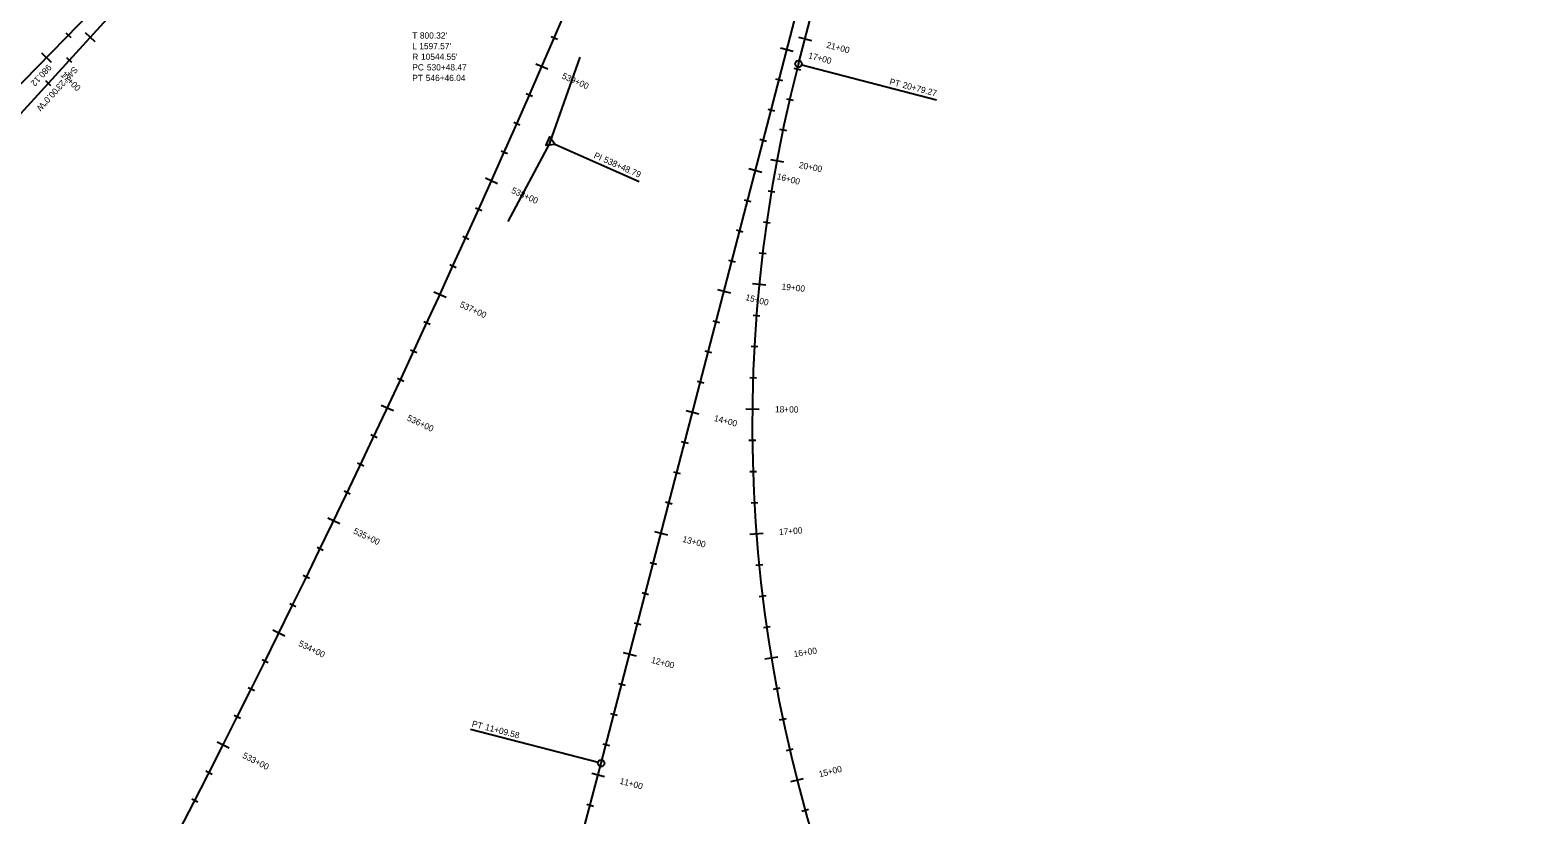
# Model space of a CAD drawing. Extents: x 2300830 to 2307917, y 756066 to 766359.
# Drawn here: x 2303759 to 2304965, y 762132 to 762760 of the extents above; entities that cross this region are included whole.
import ezdxf

# ---------------------------------------------------------------- set-up
doc = ezdxf.new("R2010")
doc.units = 0
for name, color, linetype in [('Default', 7, 'Continuous'), ('Draft_Bearing Label', 7, 'Continuous'), ('Draft_Curve Data Label', 7, 'Continuous'), ('Draft_Station Cardinal Lines', 7, 'Continuous'), ('Draft_Station Cardinal Points', 7, 'Continuous'), ('Draft_Station Labels Major', 7, 'Continuous'), ('Draft_Station Ticks Major', 7, 'Continuous'), ('Draft_Station Ticks Minor', 7, 'Continuous'), ('Geom_Baseline', 7, 'Continuous')]:
    doc.layers.add(name, color=color, linetype=linetype)

msp = doc.modelspace()

# ---------------------------------------------------------------- linework, layer by layer
at = {"layer": 'Default'}
for p, q in [((2304215.7, 762173.2), (2304540, 763420.7)), ((2304103.9, 763080), (2303443.2, 762356)), ((2303597.1, 762560.2), (2304068.2, 763040.9)), ((2304373.6, 762733), (2304449.9, 763026.4))]:
    msp.add_line(p, q, dxfattribs=at)
for centre, radius, start, end in [((2294501, 766942), 10544.6, 331.8357, 340.5164), ((2305484.2, 762444.3), 1147.5, 165.4287, 243.12), ((2304169.7, 761693), 983.5, 137.6167, 272.5224), ((2298663, 763616.6), 5737.3, 339.43722, 345.42872)]:
    msp.add_arc(centre, radius, start, end, dxfattribs=at)
at = {"layer": 'Draft_Station Cardinal Lines'}
for p, q in [((2304174.8, 762670.5), (2304198.9, 762738.4)), ((2304376.2, 762732.3), (2304484, 762704.3)), ((2304174.8, 762670.5), (2304140.9, 762607)), ((2304178.7, 762668.8), (2304246.2, 762639)), ((2304213.2, 762173.8), (2304111.2, 762200.3))]:
    msp.add_line(p, q, dxfattribs=at)
msp.add_lwpolyline([(2304178.6, 762668.8), (2304174.4, 762674.7), (2304171.5, 762668.1)], close=True, dxfattribs=at)
at = {"layer": 'Draft_Station Cardinal Points'}
for p, q in [((2304373.6, 762733), (2304373.6, 762733)), ((2304484, 762704.3), (2304484, 762704.3)), ((2304174.8, 762670.5), (2304174.8, 762670.5)), ((2304246.2, 762639), (2304246.2, 762639)), ((2304111.2, 762200.3), (2304111.2, 762200.3)), ((2304215.7, 762173.2), (2304215.7, 762173.2))]:
    msp.add_line(p, q, dxfattribs=at)
for centre in [(2304373.6, 762733), (2304215.7, 762173.2)]:
    msp.add_circle(centre, 2.67, dxfattribs=at)
at = {"layer": 'Draft_Station Ticks Major'}
for p, q in [((2303810.8, 762750.8), (2303802.9, 762758)), ((2304373.7, 762754.4), (2304383.9, 762751.7)), ((2303767.8, 762742), (2303775.4, 762734.5)), ((2304359.1, 762745.9), (2304369.4, 762743.3)), ((2304163.4, 762733.2), (2304173.1, 762729)), ((2304351.1, 762656.6), (2304361.5, 762654.6)), ((2304334, 762649.2), (2304344.2, 762646.5)), ((2304123, 762641.8), (2304132.7, 762637.4)), ((2304081.8, 762550.7), (2304091.5, 762546.3)), ((2304308.8, 762552.4), (2304319.1, 762549.7)), ((2304336.9, 762557.2), (2304347.5, 762556.1)), ((2304039.7, 762460), (2304049.4, 762455.5)), ((2304283.6, 762455.6), (2304293.9, 762452.9)), ((2304331.4, 762456.9), (2304342.1, 762456.8)), ((2303996.8, 762369.8), (2304006.4, 762365.2)), ((2304258.5, 762358.8), (2304268.8, 762356.1)), ((2304334.7, 762356.5), (2304345.3, 762357.3)), ((2303953, 762279.9), (2303962.6, 762275.2)), ((2304233.3, 762262), (2304243.6, 762259.3)), ((2304346.7, 762256.8), (2304357.2, 762258.5)), ((2303908.4, 762190.5), (2303917.9, 762185.7)), ((2304208.2, 762165.2), (2304218.4, 762162.6)), ((2304367.4, 762158.5), (2304377.6, 762161.1))]:
    msp.add_line(p, q, dxfattribs=at)
at = {"layer": 'Draft_Station Ticks Minor'}
for p, q in [((2303787.2, 762758), (2303791.1, 762754.2)), ((2304175.7, 762755.1), (2304180.8, 762752.9)), ((2303792, 762734.1), (2303787.9, 762737.8)), ((2304369.9, 762729.5), (2304375.2, 762728.2)), ((2303775.1, 762715.6), (2303771.1, 762719.4)), ((2304355.3, 762721.1), (2304360.7, 762719.7)), ((2304155.7, 762709.3), (2304160.8, 762707.1)), ((2304363.9, 762705.2), (2304369.3, 762703.9)), ((2304349, 762696.9), (2304354.4, 762695.5)), ((2304145.7, 762686.4), (2304150.7, 762684.2)), ((2304358.5, 762680.7), (2304363.9, 762679.6)), ((2304342.7, 762672.7), (2304348.1, 762671.3)), ((2304135.6, 762663.5), (2304140.6, 762661.3)), ((2304349.3, 762631.4), (2304354.7, 762630.6)), ((2304330.2, 762624.3), (2304335.5, 762622.9)), ((2304115.2, 762617.9), (2304120.2, 762615.6)), ((2304345.5, 762606.7), (2304350.9, 762605.9)), ((2304104.9, 762595.1), (2304109.9, 762592.8)), ((2304323.9, 762600.1), (2304329.2, 762598.7)), ((2304094.6, 762572.4), (2304099.6, 762570.1)), ((2304317.6, 762575.9), (2304322.9, 762574.5)), ((2304342.2, 762581.8), (2304347.7, 762581.2)), ((2304073.7, 762526.9), (2304078.7, 762524.6)), ((2304305, 762527.5), (2304310.3, 762526.1)), ((2304337.3, 762532), (2304342.8, 762531.5)), ((2304063.2, 762504.2), (2304068.2, 762501.9)), ((2304298.7, 762503.3), (2304304.1, 762501.9)), ((2304335.7, 762507), (2304341.2, 762506.7)), ((2304052.7, 762481.6), (2304057.7, 762479.2)), ((2304292.4, 762479.1), (2304297.8, 762477.7)), ((2304334.6, 762481.9), (2304340.1, 762481.7)), ((2304031.4, 762436.3), (2304036.4, 762434)), ((2304279.8, 762430.7), (2304285.2, 762429.4)), ((2304334, 762431.8), (2304339.5, 762431.9)), ((2304020.7, 762413.8), (2304025.7, 762411.4)), ((2304273.6, 762406.5), (2304278.9, 762405.2)), ((2304334.6, 762406.8), (2304340.1, 762406.9)), ((2304010, 762391.2), (2304014.9, 762388.8)), ((2304267.3, 762382.4), (2304272.6, 762381)), ((2304335.7, 762381.7), (2304341.2, 762382)), ((2303988.3, 762346.2), (2303993.2, 762343.8)), ((2304254.7, 762334), (2304260, 762332.6)), ((2304339.5, 762331.7), (2304345, 762332.3)), ((2303977.3, 762323.7), (2303982.3, 762321.3)), ((2304248.4, 762309.8), (2304253.7, 762308.4)), ((2304342.2, 762306.8), (2304347.7, 762307.5)), ((2303966.4, 762301.2), (2303971.3, 762298.8)), ((2304242.1, 762285.6), (2304247.4, 762284.2)), ((2304345.5, 762282), (2304350.9, 762282.8)), ((2303944.3, 762256.4), (2303949.2, 762253.9)), ((2303933.1, 762234), (2303938.1, 762231.6)), ((2304229.5, 762237.2), (2304234.9, 762235.8)), ((2304353.6, 762232.5), (2304359, 762233.6)), ((2303921.9, 762211.7), (2303926.9, 762209.2)), ((2304223.2, 762213), (2304228.6, 762211.6)), ((2304358.5, 762208), (2304363.9, 762209.1)), ((2304216.9, 762188.8), (2304222.3, 762187.4)), ((2304363.9, 762183.5), (2304369.3, 762184.7)), ((2303899.4, 762167.1), (2303904.3, 762164.6)), ((2303888.1, 762144.8), (2303893, 762142.3)), ((2304204.3, 762140.4), (2304209.6, 762139)), ((2304376.3, 762134.9), (2304381.6, 762136.4))]:
    msp.add_line(p, q, dxfattribs=at)
at = {"layer": 'Geom_Baseline'}
for p, q in [((2304215.7, 762173.2), (2304540, 763420.7)), ((2304103.9, 763080), (2303443.2, 762356)), ((2303597.1, 762560.2), (2304068.2, 763040.9)), ((2304373.6, 762733), (2304449.9, 763026.4))]:
    msp.add_line(p, q, dxfattribs=at)
for centre, radius, start, end in [((2294501, 766942), 10544.6, 331.8357, 340.5164), ((2305484.2, 762444.3), 1147.5, 165.4287, 243.12), ((2304169.7, 761693), 983.5, 137.6167, 272.5224), ((2298663, 763616.6), 5737.3, 339.43722, 345.42872)]:
    msp.add_arc(centre, radius, start, end, dxfattribs=at)

# ---------------------------------------------------------------- texts
at = {"layer": 'Draft_Bearing Label'}
for s, p in [('980.12', (2303772.6, 762733.1)), ('S42°23\'00.0"W', (2303793.7, 762731.4))]:
    msp.add_text(s, height=5, rotation=227.6167, dxfattribs=at).set_placement(p)
at = {"layer": 'Draft_Curve Data Label'}
for s, p in [('T ', (2304064.5, 762753.3)), ("800.32'", (2304070.6, 762753.3)), ('L ', (2304064.5, 762744.8)), ('R ', (2304064.5, 762736.3)), ("1597.57'", (2304070.1, 762744.8)), ("10544.55'", (2304071.5, 762736.3)), ('PC ', (2304064.5, 762727.8)), ('530+48.47', (2304076.2, 762727.8)), ('PT ', (2304064.5, 762719.3)), ('546+46.04', (2304075.3, 762719.3))]:
    msp.add_text(s, height=5, dxfattribs=at).set_placement(p)
at = {"layer": 'Draft_Station Cardinal Points'}
for s, rotation, p in [('PT', 345.4287, (2304446, 762716.7)), ('20+79.27', 345.4287, (2304456.5, 762714)), ('PI ', 336.176, (2304209.3, 762658)), ('538+48.79', 336.176, (2304217.1, 762654.6)), ('PT', 345.4287, (2304111.8, 762202.7)), ('11+09.58', 345.4287, (2304122.4, 762200))]:
    msp.add_text(s, height=5, rotation=rotation, dxfattribs=at).set_placement(p)
at = {"layer": 'Draft_Station Labels Major'}
for s, rotation, p in [('17+00', 345.4287, (2304381.1, 762737.6)), ('21+00', 345.4287, (2304395.6, 762746.1)), ('17+00', 315.579, (2303782.7, 762723.9)), ('539+00', 336.4626, (2304183.8, 762721.6)), ('20+00', 349.3867, (2304373.6, 762649.8)), ('16+00', 345.4287, (2304355.9, 762640.9)), ('538+00', 335.9193, (2304143.3, 762630)), ('15+00', 345.4287, (2304330.8, 762544.1)), ('19+00', 354.38, (2304359.9, 762552.4)), ('537+00', 335.3759, (2304102, 762538.7)), ('536+00', 334.8325, (2304059.8, 762447.9)), ('14+00', 345.4287, (2304305.6, 762447.3)), ('18+00', 359.3733, (2304354.8, 762454.1)), ('535+00', 334.2892, (2304016.8, 762357.4)), ('13+00', 345.4287, (2304280.4, 762350.5)), ('17+00', 4.3665, (2304358.2, 762355.8)), ('534+00', 333.7458, (2303972.9, 762267.4)), ('12+00', 345.4287, (2304255.3, 762253.7)), ('16+00', 9.3598, (2304370.2, 762258.1)), ('533+00', 333.2024, (2303928.1, 762177.8)), ('11+00', 345.3331, (2304230.1, 762156.9)), ('15+00', 14.3531, (2304390.6, 762161.9))]:
    msp.add_text(s, height=5, rotation=rotation, dxfattribs=at).set_placement(p)

doc.saveas('drawing.dxf')
